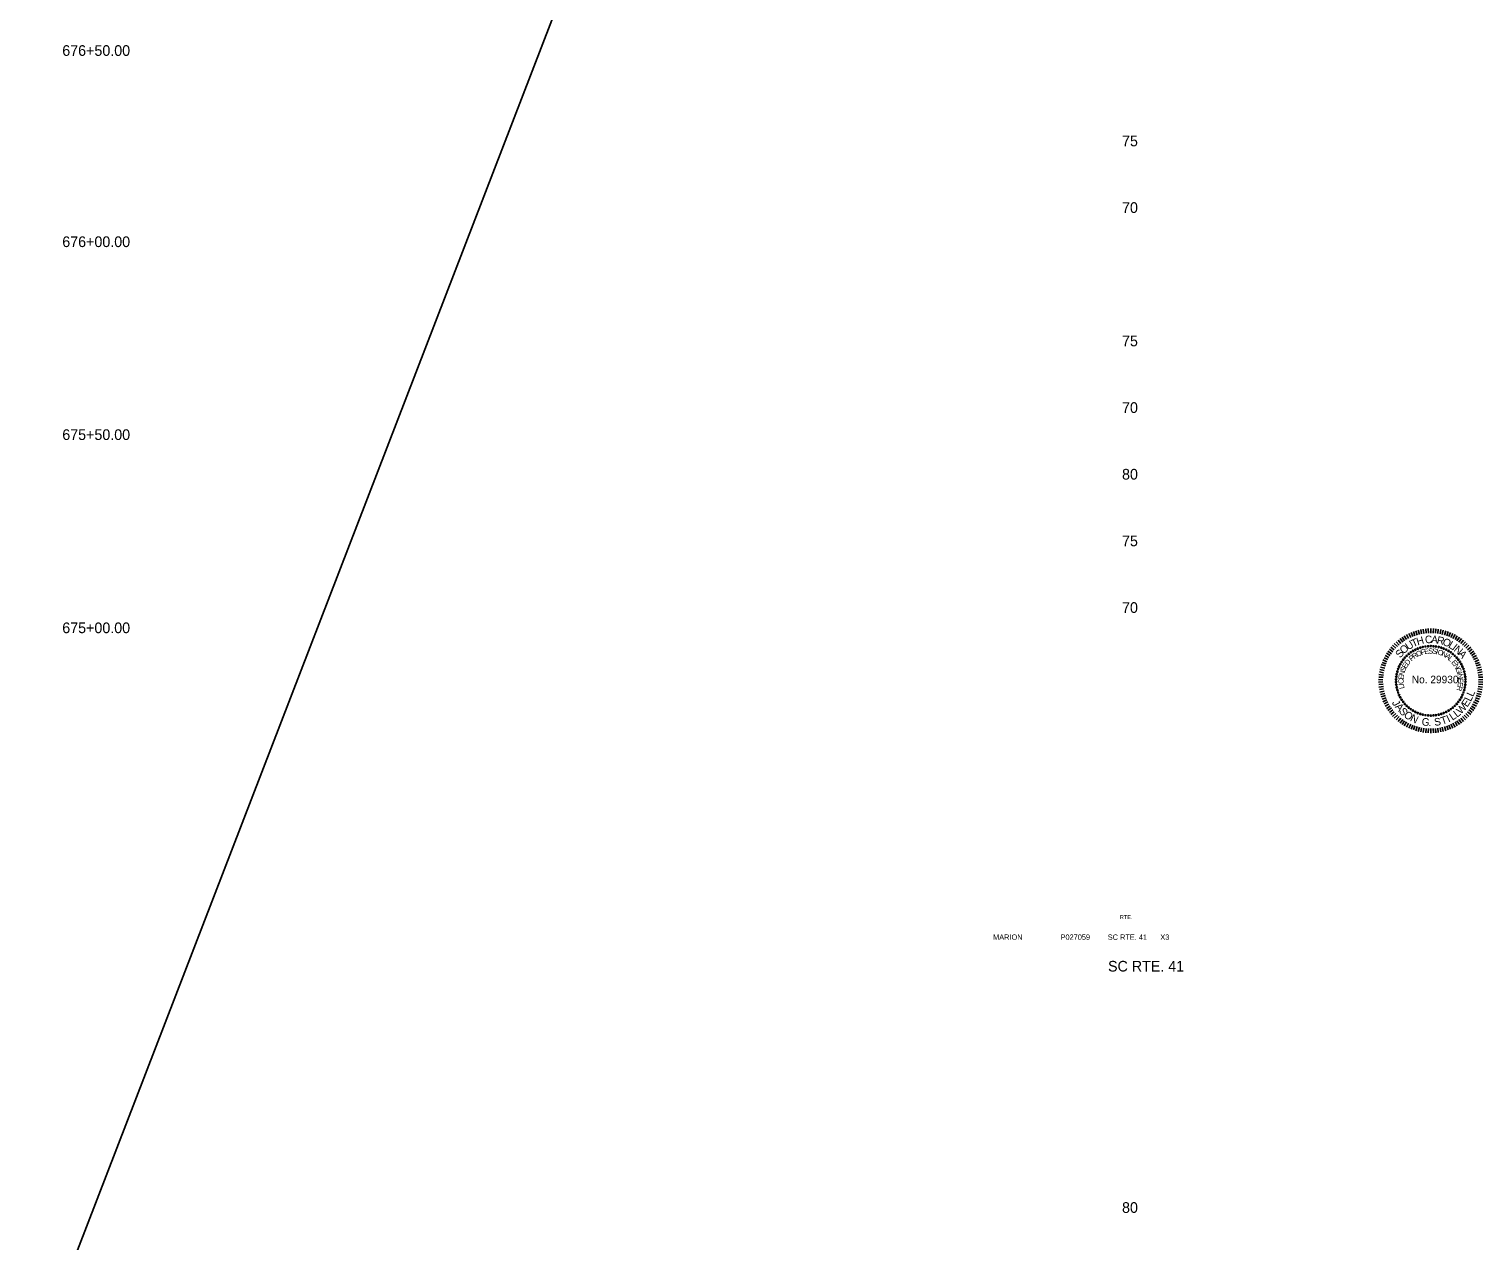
# Model space of a CAD drawing. Extents: x 952 to 1206, y 942 to 2399.
# Drawn here: x 1074.9 to 1184, y 1307.9 to 1398.8 of the extents above; entities that cross this region are included whole.
import ezdxf

# ---------------------------------------------------------------- set-up
doc = ezdxf.new("R2010")
doc.units = 0
for name, color, linetype in [('Default', 7, 'Continuous'), ('RD_SHT_TX', 7, 'Continuous'), ('RD_TX_PEShield', 7, 'Continuous'), ('RD_XS_TX_Elev_EX', 7, 'Continuous'), ('RD_XS_TX_Station', 7, 'Continuous')]:
    doc.layers.add(name, color=color, linetype=linetype)

# ---------------------------------------------------------------- blocks, each defined once
blk = doc.blocks.new('STILLWELL')
at = {"layer": 'RD_TX_PEShield'}
for p, q in [((-18.2, 30), (-19.9, 32.8)), ((-16.7, 30.8), (-18.2, 33.7)), ((-15.1, 31.6), (-16.5, 34.6)), ((-13.6, 32.3), (-14.8, 35.3)), ((-11.9, 32.9), (-13, 36)), ((-10.3, 33.4), (-11.2, 36.6)), ((-8.6, 33.9), (-9.4, 37.1)), ((-6.9, 34.3), (-7.5, 37.5)), ((-5.2, 34.6), (-5.7, 37.8)), ((-3.5, 34.8), (-3.8, 38)), ((-1.8, 34.9), (-1.9, 38.2)), ((0, 34.9), (0, 38.2)), ((1.7, 34.9), (1.9, 38.2)), ((3.4, 34.8), (3.7, 38)), ((5.2, 34.6), (5.6, 37.8)), ((6.9, 34.3), (7.5, 37.5)), ((8.6, 33.9), (9.3, 37.1)), ((10.2, 33.4), (11.2, 36.6)), ((11.9, 32.9), (13, 36)), ((13.5, 32.3), (14.7, 35.3)), ((15.1, 31.6), (16.5, 34.6)), ((16.6, 30.8), (18.2, 33.7)), ((18.2, 30), (19.8, 32.8)), ((-28.5, 20.9), (-31.1, 22.8)), ((-27.4, 22.2), (-29.9, 24.3)), ((-26.3, 23.5), (-28.7, 25.7)), ((-25.1, 24.7), (-27.4, 27.1)), ((-23.8, 25.9), (-26, 28.4)), ((-22.5, 27), (-24.5, 29.6)), ((-21.1, 28.1), (-23, 30.7)), ((-19.7, 29.1), (-21.5, 31.8)), ((19.6, 29.1), (21.4, 31.8)), ((21.1, 28.1), (23, 30.7)), ((22.4, 27), (24.5, 29.6)), ((23.8, 25.9), (25.9, 28.4)), ((25, 24.7), (27.3, 27.1)), ((26.2, 23.5), (28.6, 25.7)), ((27.4, 22.2), (29.9, 24.3)), ((28.5, 20.9), (31.1, 22.8)), ((-34.1, 10.2), (-37.2, 11.2)), ((-33.6, 11.8), (-36.6, 12.9)), ((-32.9, 13.4), (-35.9, 14.7)), ((-32.2, 15), (-35.1, 16.4)), ((-31.4, 16.5), (-34.2, 18.1)), ((-30.5, 18), (-33.3, 19.7)), ((-29.5, 19.4), (-32.2, 21.3)), ((29.5, 19.4), (32.2, 21.3)), ((30.4, 18), (33.2, 19.7)), ((31.3, 16.5), (34.2, 18.1)), ((32.1, 15), (35.1, 16.4)), ((32.9, 13.4), (35.9, 14.7)), ((33.5, 11.8), (36.6, 12.9)), ((34.1, 10.2), (37.2, 11.2)), ((-35.9, -0.1), (-39.2, 0)), ((-35.8, 1.7), (-39.1, 1.9)), ((-35.6, 3.4), (-38.9, 3.8)), ((-35.4, 5.1), (-38.6, 5.7)), ((-35.1, 6.8), (-38.2, 7.5)), ((-34.6, 8.5), (-37.8, 9.4)), ((34.6, 8.5), (37.7, 9.4)), ((35, 6.8), (38.2, 7.5)), ((35.3, 5.1), (38.5, 5.7)), ((35.6, 3.4), (38.8, 3.8)), ((35.7, 1.7), (39, 1.9)), ((35.8, -0.1), (39.1, 0)), ((-35.9, -1.8), (-39.2, -1.9)), ((-35.8, -3.5), (-39.1, -3.8)), ((-35.6, -5.3), (-38.9, -5.6)), ((-35.4, -7), (-38.6, -7.5)), ((-35.1, -8.7), (-38.2, -9.4)), ((-34.6, -10.4), (-37.8, -11.2)), ((34.6, -10.4), (37.7, -11.2)), ((35, -8.7), (38.2, -9.4)), ((35.3, -7), (38.5, -7.5)), ((35.6, -5.3), (38.8, -5.6)), ((35.7, -3.5), (39, -3.8)), ((35.8, -1.8), (39.1, -1.9)), ((-34.1, -12), (-37.2, -13)), ((-33.6, -13.6), (-36.6, -14.8)), ((-32.9, -15.3), (-35.9, -16.6)), ((-32.2, -16.8), (-35.1, -18.3)), ((-31.4, -18.4), (-34.2, -19.9)), ((-30.5, -19.9), (-33.3, -21.6)), ((-29.5, -21.3), (-32.2, -23.2)), ((29.5, -21.3), (32.2, -23.2)), ((30.4, -19.9), (33.2, -21.6)), ((31.3, -18.4), (34.2, -19.9)), ((32.1, -16.8), (35.1, -18.3)), ((32.9, -15.3), (35.9, -16.6)), ((33.5, -13.6), (36.6, -14.8)), ((34.1, -12), (37.2, -13)), ((-28.5, -22.7), (-31.1, -24.7)), ((-27.4, -24.1), (-29.9, -26.2)), ((-26.3, -25.4), (-28.7, -27.6)), ((-25.1, -26.6), (-27.4, -28.9)), ((-23.8, -27.8), (-26, -30.2)), ((-22.5, -28.9), (-24.5, -31.4)), ((-21.1, -29.9), (-23, -32.6)), ((-19.7, -30.9), (-21.5, -33.7)), ((-18.2, -31.8), (-19.9, -34.7)), ((-16.7, -32.7), (-18.2, -35.6)), ((16.6, -32.7), (18.2, -35.6)), ((18.2, -31.8), (19.8, -34.7)), ((19.6, -30.9), (21.4, -33.7)), ((21.1, -29.9), (23, -32.6)), ((22.4, -28.9), (24.5, -31.4)), ((23.8, -27.8), (25.9, -30.2)), ((25, -26.6), (27.3, -28.9)), ((26.2, -25.4), (28.6, -27.6)), ((27.4, -24.1), (29.9, -26.2)), ((28.5, -22.7), (31.1, -24.7)), ((-15.1, -33.5), (-16.5, -36.4)), ((-13.6, -34.1), (-14.8, -37.2)), ((-11.9, -34.8), (-13, -37.8)), ((-10.3, -35.3), (-11.2, -38.4)), ((-8.6, -35.8), (-9.4, -38.9)), ((-6.9, -36.1), (-7.5, -39.3)), ((-5.2, -36.4), (-5.7, -39.7)), ((-3.5, -36.6), (-3.8, -39.9)), ((-1.8, -36.8), (-1.9, -40)), ((0, -36.8), (0, -40.1)), ((1.7, -36.8), (1.9, -40)), ((3.4, -36.6), (3.7, -39.9)), ((5.2, -36.4), (5.6, -39.7)), ((6.9, -36.1), (7.5, -39.3)), ((8.6, -35.8), (9.3, -38.9)), ((10.2, -35.3), (11.2, -38.4)), ((11.9, -34.8), (13, -37.8)), ((13.5, -34.1), (14.7, -37.2)), ((15.1, -33.5), (16.5, -36.4))]:
    blk.add_line(p, q, dxfattribs=at)
for centre in [(-13.3, 21.5), (-11.6, 22.4), (-9.8, 23.2), (-7.9, 23.9), (-6, 24.4), (-4, 24.8), (-2, 25), (0, 25.1), (2, 25), (3.9, 24.8), (5.9, 24.4), (7.8, 23.9), (9.7, 23.2), (11.5, 22.4), (13.3, 21.5), (-22.9, 11.5), (-21.9, 13.2), (-20.7, 14.9), (-19.5, 16.4), (-18.1, 17.8), (-16.6, 19.2), (-15, 20.4), (15, 20.4), (16.5, 19.2), (18, 17.8), (19.4, 16.4), (20.7, 14.9), (21.8, 13.2), (22.9, 11.5), (-26.1, 0.1), (-25.9, 2.1), (-25.6, 4), (-25.1, 6), (-24.5, 7.9), (-23.8, 9.7), (23.7, 9.7), (24.5, 7.9), (25.1, 6), (25.5, 4), (25.8, 2.1), (26, 0.1), (-26.1, -1.9), (-25.9, -3.9), (-25.6, -5.9), (-25.1, -7.8), (-24.5, -9.7), (24.5, -9.7), (25.1, -7.8), (25.5, -5.9), (25.8, -3.9), (26, -1.9), (-23.8, -11.6), (-22.9, -13.4), (-21.9, -15.1), (-20.7, -16.7), (-19.5, -18.3), (-18.1, -19.7), (-16.6, -21), (-15, -22.2), (15, -22.2), (16.5, -21), (18, -19.7), (19.4, -18.3), (20.7, -16.7), (21.8, -15.1), (22.9, -13.4), (23.7, -11.6), (-13.3, -23.3), (-11.6, -24.3), (-9.8, -25.1), (-7.9, -25.8), (-6, -26.3), (-4, -26.7), (-2, -26.9), (0, -27), (2, -26.9), (3.9, -26.7), (5.9, -26.3), (7.8, -25.8), (9.7, -25.1), (11.5, -24.3), (13.3, -23.3)]:
    blk.add_circle(centre, 0.49, dxfattribs=at)
for s, height, rotation, p in [('C', 5.68, 4.076, (-4.2, 27.1)), ('A', 5.68, 355.3651, (0.1, 27.4)), ('S', 5.68, 49.6435, (-22.9, 15.8)), ('O', 5.68, 41.5972, (-20.4, 18.8)), ('U', 5.68, 32.2152, (-16.9, 21.8)), ('T', 5.68, 23.5044, (-13.2, 24.1)), ('H', 5.68, 16.1357, (-9.9, 25.6)), ('F', 3.92, 15.9995, (-7.1, 18.3)), ('E', 3.92, 8.9511, (-4.7, 19)), ('S', 3.92, 1.2546, (-1.9, 19.4)), ('S', 3.92, 353.558, (0.8, 19.5)), ('I', 3.92, 345.8615, (3.5, 19.2)), ('R', 5.68, 347.3188, (4.1, 27.1)), ('O', 3.92, 342.6583, (4.7, 19)), ('O', 5.68, 338.6079, (8.3, 26.2)), ('L', 5.68, 329.226, (12.6, 24.4)), ('I', 5.68, 322.5218, (15.5, 22.8)), ('N', 5.68, 319.1729, (16.8, 21.8)), ('E', 3.92, 60.2341, (-18.5, 7.9)), ('D', 3.92, 52.5376, (-17.1, 10.3)), ('P', 3.92, 41.0022, (-14.5, 13.5)), ('R', 3.92, 33.3057, (-12.5, 15.3)), ('O', 3.92, 24.9735, (-10, 16.9)), ('N', 3.92, 333.6842, (7.7, 18)), ('A', 3.92, 325.3521, (10.4, 16.7)), ('L', 3.92, 317.6555, (12.6, 15.1)), ('E', 3.92, 308.0396, (15.1, 12.8)), ('N', 3.92, 300.343, (16.8, 10.6)), ('A', 5.68, 310.4621, (20.1, 19)), ('C', 3.92, 92.2915, (-20.4, -3.2)), ('E', 3.92, 83.9594, (-20.5, -0.2)), ('N', 3.92, 76.2628, (-20.2, 2.5)), ('S', 3.92, 67.9307, (-19.5, 5.4)), ('G', 3.92, 292.0109, (18.3, 8.1)), ('I', 3.92, 283.0368, (19.5, 5.1)), ('N', 3.92, 279.8336, (19.8, 4)), ('E', 3.92, 271.5014, (20.3, 1.1)), ('I', 3.92, 95.4947, (-20.2, -4.3)), ('L', 3.92, 101.9075, (-19.7, -6.6)), ('R', 3.92, 256.1083, (20.1, -4.4)), ('E', 3.92, 263.8049, (20.4, -1.7)), ('L', 5.68, 65.098, (31.6, -13.3)), ('J', 5.68, 299.033, (-29.4, -17.3)), ('A', 5.68, 310.5887, (-27.2, -20.6)), ('S', 5.68, 310.5887, (-24.3, -24)), ('W', 5.68, 47.0518, (22.6, -26.4)), ('E', 5.68, 56.4327, (27.3, -21.1)), ('L', 5.68, 65.098, (30, -16.9)), ('O', 5.68, 321.0072, (-20.8, -27.4)), ('N', 5.68, 333.4326, (-16, -30.8)), ('G', 5.68, 352.2045, (-7.2, -34.2)), ('S', 5.68, 8.0826, (2.9, -34.8)), ('T', 5.68, 18.9019, (8.5, -33.9)), ('I', 5.68, 25.3991, (13.3, -32.2)), ('L', 5.68, 34.0644, (16.2, -30.9)), ('L', 5.68, 37.6708, (19.6, -28.7)), ('.', 5.68, 0.8698, (-1.8, -34.9))]:
    blk.add_text(s, height=height, rotation=rotation, dxfattribs=at).set_placement(p)
blk.add_text('No. 29930', height=5.68, dxfattribs=at).set_placement((-14.3, -2.8))

msp = doc.modelspace()

# ---------------------------------------------------------------- linework, layer by layer
at = {"layer": 'RD_SHT_TX'}
msp.add_line((951.99, 979.01), (1182.92, 1577.73), dxfattribs=at)

# ---------------------------------------------------------------- block references
at = {"layer": 'Default', "xscale": 0.1, "yscale": 0.10000000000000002}
msp.add_blockref('STILLWELL', (1180.08, 1350), dxfattribs=at)

# ---------------------------------------------------------------- texts
at = {"layer": 'RD_SHT_TX'}
for s, height, p in [('RTE.', 0.3, (1156.76, 1332.03)), ('MARION', 0.4, (1147.25, 1330.48)), ('P027059', 0.4, (1152.31, 1330.48)), ('SC RTE. 41', 0.4, (1155.85, 1330.48)), ('X3', 0.4, (1159.79, 1330.48)), ('SC RTE. 41', 0.8, (1155.87, 1328.1))]:
    msp.add_text(s, height=height, dxfattribs=at).set_placement(p)
at = {"layer": 'RD_XS_TX_Elev_EX'}
for s, p in [('75', (1156.92, 1390)), ('70', (1156.92, 1385)), ('75', (1156.92, 1375)), ('70', (1156.92, 1370)), ('80', (1156.92, 1365)), ('75', (1156.92, 1360)), ('70', (1156.92, 1355)), ('80', (1156.92, 1310))]:
    msp.add_text(s, height=0.8, dxfattribs=at).set_placement(p)
at = {"layer": 'RD_XS_TX_Station'}
for s, p in [('676+50.00', (1077.44, 1396.78)), ('676+00.00', (1077.44, 1382.44)), ('675+50.00', (1077.44, 1367.97)), ('675+00.00', (1077.44, 1353.48))]:
    msp.add_text(s, height=0.8, dxfattribs=at).set_placement(p)

doc.saveas('drawing.dxf')
